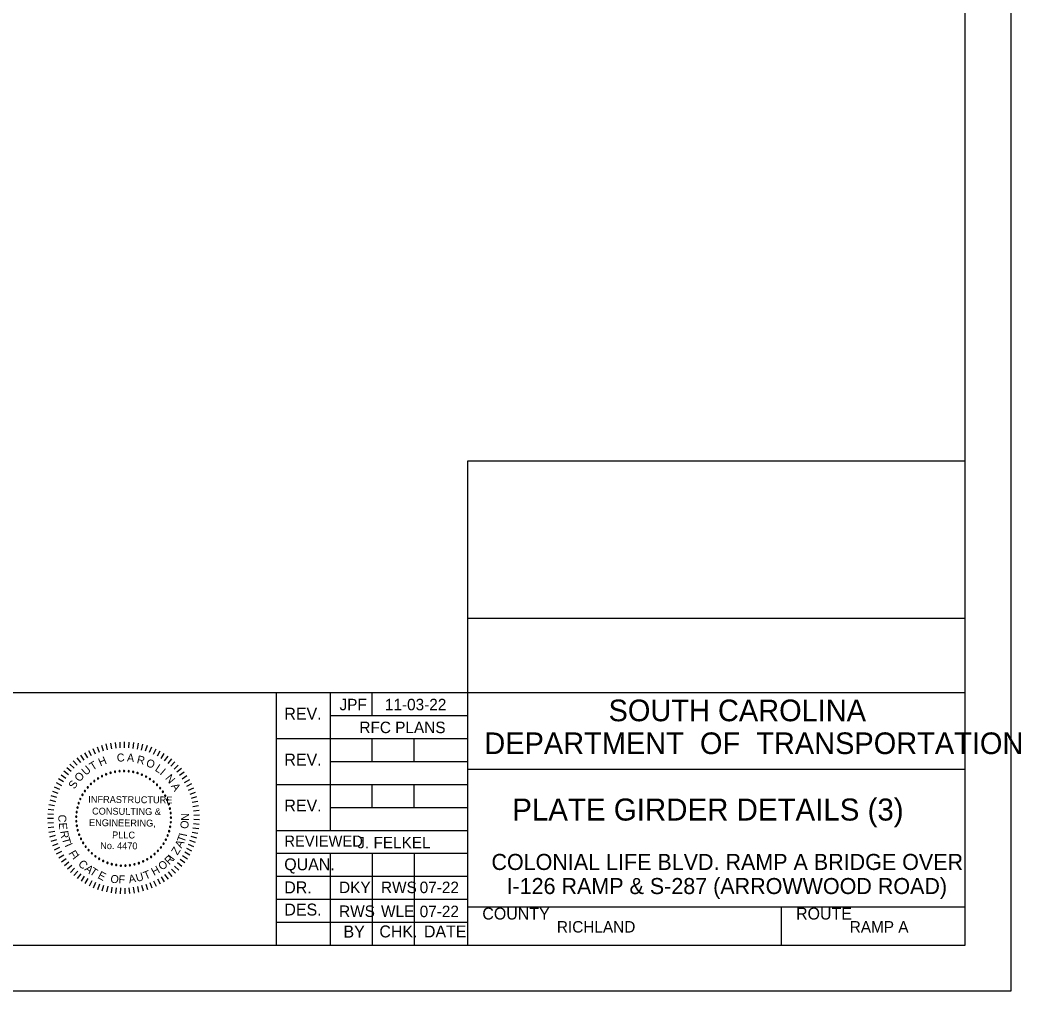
# Model space of a CAD drawing. Extents: x -383 to 7, y -330 to -94.
# Drawn here: x -204.36 to -160.75, y -187.49 to -145.18 of the extents above; entities that cross this region are included whole.
import ezdxf

# ---------------------------------------------------------------- set-up
doc = ezdxf.new("R2010")
doc.units = 0
for name, color, linetype in [('BR_BORDER LINES', 7, 'Continuous'), ('BR_TEXT', 7, 'Continuous'), ('Level 31', 7, 'Continuous')]:
    doc.layers.add(name, color=color, linetype=linetype)

msp = doc.modelspace()

# ---------------------------------------------------------------- linework, layer by layer
at = {"layer": 'BR_BORDER LINES'}
for p, q in [((-163.178, -185.489), (-163.178, -101.489)), ((-184.846, -185.489), (-184.846, -164.383)), ((-184.846, -164.383), (-163.178, -164.383)), ((-184.845, -171.242), (-163.178, -171.242)), ((-214.64, -174.489), (-193.18, -174.489)), ((-193.18, -185.489), (-193.18, -174.489)), ((-193.18, -174.489), (-163.178, -174.489)), ((-190.846, -174.489), (-190.846, -180.489)), ((-189.013, -175.489), (-189.013, -174.489)), ((-190.846, -175.489), (-184.846, -175.489)), ((-193.18, -176.489), (-184.846, -176.489)), ((-189.013, -177.489), (-189.013, -176.489)), ((-187.179, -177.489), (-187.179, -176.489)), ((-190.846, -177.489), (-184.846, -177.489)), ((-184.846, -177.822), (-184.846, -177.822)), ((-184.846, -177.823), (-163.178, -177.823)), ((-193.18, -178.489), (-184.846, -178.489)), ((-189.013, -179.489), (-189.013, -178.489)), ((-187.179, -179.489), (-187.179, -178.489)), ((-190.846, -179.489), (-184.846, -179.489)), ((-193.18, -180.489), (-184.846, -180.489)), ((-193.18, -181.489), (-184.846, -181.489)), ((-190.846, -181.489), (-190.846, -185.489)), ((-189.013, -181.489), (-189.013, -185.489)), ((-187.179, -181.489), (-187.179, -185.489)), ((-193.18, -182.489), (-184.846, -182.489)), ((-193.18, -183.489), (-184.846, -183.489)), ((-184.846, -183.823), (-163.178, -183.823)), ((-184.456, -183.823), (-163.178, -183.823)), ((-171.179, -185.489), (-171.179, -183.823)), ((-193.18, -184.489), (-184.846, -184.489)), ((-297.843, -185.489), (-163.178, -185.489))]:
    msp.add_line(p, q, dxfattribs=at)
at = {"layer": 'BR_TEXT'}
for p, q in [((-201.37, -177.007), (-201.252, -177.233)), ((-201.188, -176.92), (-201.084, -177.153)), ((-201.001, -176.844), (-200.912, -177.082)), ((-200.81, -176.779), (-200.735, -177.023)), ((-200.615, -176.726), (-200.555, -176.974)), ((-200.417, -176.685), (-200.373, -176.936)), ((-200.217, -176.656), (-200.188, -176.909)), ((-200.016, -176.64), (-200.002, -176.894)), ((-199.814, -176.636), (-199.816, -176.89)), ((-199.612, -176.644), (-199.63, -176.898)), ((-199.411, -176.664), (-199.444, -176.917)), ((-199.212, -176.697), (-199.26, -176.947)), ((-199.015, -176.741), (-199.079, -176.988)), ((-198.821, -176.798), (-198.9, -177.04)), ((-198.631, -176.866), (-198.724, -177.103)), ((-198.446, -176.946), (-198.553, -177.177)), ((-198.265, -177.037), (-198.387, -177.261)), ((-202.035, -177.463), (-201.866, -177.654)), ((-201.879, -177.334), (-201.723, -177.535)), ((-201.716, -177.215), (-201.572, -177.425)), ((-201.546, -177.106), (-201.415, -177.324)), ((-198.091, -177.139), (-198.226, -177.355)), ((-197.923, -177.251), (-198.071, -177.458)), ((-197.762, -177.373), (-197.922, -177.571)), ((-202.45, -177.903), (-202.25, -178.06)), ((-202.321, -177.748), (-202.13, -177.917)), ((-202.182, -177.601), (-202.002, -177.781)), ((-197.609, -177.505), (-197.781, -177.693)), ((-197.464, -177.646), (-197.647, -177.823)), ((-197.329, -177.795), (-197.522, -177.961)), ((-202.679, -178.235), (-202.461, -178.366)), ((-202.57, -178.065), (-202.36, -178.21)), ((-197.202, -177.952), (-197.405, -178.106)), ((-197.086, -178.117), (-197.298, -178.258)), ((-196.979, -178.289), (-197.199, -178.417)), ((-202.944, -178.779), (-202.705, -178.869)), ((-202.867, -178.593), (-202.634, -178.696)), ((-202.779, -178.411), (-202.553, -178.529)), ((-196.883, -178.467), (-197.111, -178.581)), ((-196.799, -178.65), (-197.033, -178.75)), ((-203.063, -179.165), (-202.815, -179.225)), ((-203.009, -178.97), (-202.766, -179.045)), ((-196.725, -178.838), (-196.965, -178.924)), ((-196.664, -179.03), (-196.908, -179.101)), ((-203.134, -179.562), (-202.881, -179.592)), ((-203.104, -179.363), (-202.853, -179.407)), ((-196.614, -179.226), (-196.862, -179.282)), ((-196.576, -179.424), (-196.827, -179.465)), ((-196.55, -179.625), (-196.804, -179.65)), ((-203.156, -179.965), (-202.901, -179.964)), ((-203.151, -179.764), (-202.897, -179.777)), ((-196.537, -179.826), (-196.791, -179.836)), ((-196.535, -180.028), (-196.79, -180.022)), ((-203.149, -180.167), (-202.895, -180.15)), ((-203.129, -180.368), (-202.877, -180.335)), ((-203.097, -180.568), (-202.847, -180.52)), ((-196.57, -180.43), (-196.822, -180.393)), ((-196.547, -180.23), (-196.8, -180.208)), ((-203.053, -180.765), (-202.807, -180.701)), ((-202.997, -180.959), (-202.755, -180.881)), ((-196.713, -181.018), (-196.954, -180.936)), ((-196.653, -180.825), (-196.899, -180.758)), ((-196.606, -180.629), (-196.855, -180.577)), ((-202.93, -181.149), (-202.693, -181.056)), ((-202.851, -181.335), (-202.62, -181.228)), ((-202.761, -181.516), (-202.536, -181.395)), ((-196.867, -181.392), (-197.096, -181.281)), ((-196.784, -181.207), (-197.02, -181.111)), ((-202.66, -181.69), (-202.443, -181.556)), ((-202.548, -181.859), (-202.34, -181.711)), ((-197.179, -181.91), (-197.385, -181.759)), ((-197.065, -181.743), (-197.279, -181.605)), ((-196.96, -181.57), (-197.182, -181.446)), ((-202.426, -182.02), (-202.228, -181.86)), ((-202.295, -182.173), (-202.107, -182.002)), ((-202.155, -182.319), (-201.977, -182.136)), ((-202.006, -182.455), (-201.84, -182.262)), ((-197.581, -182.362), (-197.756, -182.176)), ((-197.438, -182.219), (-197.623, -182.045)), ((-197.304, -182.068), (-197.5, -181.905)), ((-201.849, -182.582), (-201.695, -182.379)), ((-201.685, -182.699), (-201.543, -182.487)), ((-201.513, -182.806), (-201.385, -182.586)), ((-201.336, -182.903), (-201.221, -182.675)), ((-198.411, -182.93), (-198.522, -182.701)), ((-198.232, -182.837), (-198.356, -182.615)), ((-198.059, -182.734), (-198.196, -182.519)), ((-197.892, -182.62), (-198.042, -182.414)), ((-197.733, -182.495), (-197.895, -182.3)), ((-201.153, -182.988), (-201.053, -182.754)), ((-200.965, -183.062), (-200.879, -182.822)), ((-200.773, -183.125), (-200.702, -182.88)), ((-200.577, -183.175), (-200.521, -182.927)), ((-200.379, -183.214), (-200.338, -182.962)), ((-200.179, -183.24), (-200.154, -182.987)), ((-199.978, -183.254), (-199.968, -183)), ((-199.776, -183.256), (-199.781, -183.002)), ((-199.574, -183.246), (-199.595, -182.992)), ((-199.373, -183.223), (-199.41, -182.971)), ((-199.174, -183.188), (-199.226, -182.939)), ((-198.978, -183.142), (-199.045, -182.896)), ((-198.785, -183.083), (-198.867, -182.842)), ((-198.596, -183.012), (-198.692, -182.777))]:
    msp.add_line(p, q, dxfattribs=at)
for centre, start, end in [((-200.22, -177.935), 10.6038, 190.6038), ((-200.023, -177.908), 5.0653, 185.0653), ((-200.023, -177.908), 185.0653, 5.0653), ((-199.824, -177.9), 359.5268, 179.5268), ((-199.824, -177.9), 179.5268, 359.5268), ((-199.625, -177.912), 353.9884, 173.9884), ((-199.625, -177.912), 173.9884, 353.9884), ((-199.428, -177.943), 348.4499, 168.4499), ((-201.12, -178.341), 38.2961, 218.2961), ((-201.12, -178.341), 218.2961, 38.2961), ((-200.957, -178.226), 32.7576, 212.7576), ((-200.957, -178.226), 212.7576, 32.7576), ((-200.785, -178.127), 27.2191, 207.2191), ((-200.785, -178.127), 207.2191, 27.2191), ((-200.603, -178.045), 21.6807, 201.6807), ((-200.603, -178.045), 201.6807, 21.6807), ((-200.414, -177.98), 16.1422, 196.1422), ((-200.414, -177.98), 196.1422, 16.1422), ((-200.22, -177.935), 190.6038, 10.6038), ((-199.428, -177.943), 168.4499, 348.4499), ((-199.235, -177.992), 162.9114, 342.9114), ((-199.235, -177.992), 342.9114, 162.9114), ((-199.047, -178.06), 157.373, 337.373), ((-199.047, -178.06), 337.373, 157.373), ((-198.867, -178.146), 151.8345, 331.8345), ((-198.867, -178.146), 331.8345, 151.8345), ((-198.697, -178.249), 146.2961, 326.2961), ((-198.697, -178.249), 326.2961, 146.2961), ((-198.537, -178.368), 140.7576, 320.7576), ((-198.537, -178.368), 320.7576, 140.7576), ((-201.53, -178.774), 54.9114, 234.9114), ((-201.53, -178.774), 234.9114, 54.9114), ((-201.408, -178.617), 49.373, 229.373), ((-201.408, -178.617), 229.373, 49.373), ((-201.27, -178.472), 43.8345, 223.8345), ((-201.27, -178.472), 223.8345, 43.8345), ((-198.389, -178.502), 135.2191, 315.2191), ((-198.389, -178.502), 315.2191, 135.2191), ((-198.255, -178.649), 129.6807, 309.6807), ((-198.255, -178.649), 309.6807, 129.6807), ((-198.135, -178.809), 124.1422, 304.1422), ((-198.135, -178.809), 304.1422, 124.1422), ((-201.727, -179.12), 65.9884, 245.9884), ((-201.727, -179.12), 245.9884, 65.9884), ((-201.637, -178.942), 60.4499, 240.4499), ((-201.637, -178.942), 240.4499, 60.4499), ((-198.032, -178.979), 118.6038, 298.6038), ((-198.032, -178.979), 298.6038, 118.6038), ((-197.945, -179.159), 113.0653, 293.0653), ((-197.945, -179.159), 293.0653, 113.0653), ((-201.854, -179.497), 77.0653, 257.0653), ((-201.854, -179.497), 257.0653, 77.0653), ((-201.8, -179.305), 71.5268, 251.5268), ((-201.8, -179.305), 251.5268, 71.5268), ((-197.876, -179.346), 107.5268, 287.5268), ((-197.876, -179.346), 287.5268, 107.5268), ((-197.826, -179.538), 101.9884, 281.9884), ((-197.826, -179.538), 281.9884, 101.9884), ((-201.906, -179.892), 88.1422, 268.1422), ((-201.904, -180.091), 93.6807, 273.6807), ((-201.89, -179.693), 82.6038, 262.6038), ((-201.906, -179.892), 268.1422, 88.1422), ((-201.904, -180.091), 273.6807, 93.6807), ((-201.89, -179.693), 262.6038, 82.6038), ((-197.795, -179.735), 96.4499, 276.4499), ((-197.782, -179.934), 90.9114, 270.9114), ((-197.795, -179.735), 276.4499, 96.4499), ((-197.782, -179.934), 270.9114, 90.9114), ((-201.882, -180.289), 99.2191, 279.2191), ((-201.882, -180.289), 279.2191, 99.2191), ((-201.841, -180.484), 104.7576, 284.7576), ((-201.841, -180.484), 284.7576, 104.7576), ((-197.86, -180.525), 74.2961, 254.2961), ((-197.86, -180.525), 254.2961, 74.2961), ((-197.815, -180.331), 79.8345, 259.8345), ((-197.815, -180.331), 259.8345, 79.8345), ((-197.789, -180.133), 85.373, 265.373), ((-197.789, -180.133), 265.373, 85.373), ((-201.781, -180.675), 110.2961, 290.2961), ((-201.781, -180.675), 290.2961, 110.2961), ((-201.703, -180.858), 115.8345, 295.8345), ((-201.703, -180.858), 295.8345, 115.8345), ((-198.005, -180.896), 63.2191, 243.2191), ((-198.005, -180.896), 243.2191, 63.2191), ((-197.924, -180.714), 68.7576, 248.7576), ((-197.924, -180.714), 248.7576, 68.7576), ((-201.608, -181.033), 121.373, 301.373), ((-201.608, -181.033), 301.373, 121.373), ((-201.497, -181.199), 126.9114, 306.9114), ((-201.497, -181.199), 306.9114, 126.9114), ((-201.37, -181.352), 132.4499, 312.4499), ((-201.37, -181.352), 312.4499, 132.4499), ((-198.349, -181.383), 46.6038, 226.6038), ((-198.349, -181.383), 226.6038, 46.6038), ((-198.219, -181.232), 52.1422, 232.1422), ((-198.219, -181.232), 232.1422, 52.1422), ((-198.104, -181.069), 57.6807, 237.6807), ((-198.104, -181.069), 237.6807, 57.6807), ((-201.228, -181.493), 137.9884, 317.9884), ((-201.228, -181.493), 317.9884, 137.9884), ((-201.074, -181.619), 143.5268, 323.5268), ((-201.074, -181.619), 323.5268, 143.5268), ((-200.909, -181.73), 149.0653, 329.0653), ((-200.909, -181.73), 329.0653, 149.0653), ((-200.733, -181.825), 154.6038, 334.6038), ((-200.733, -181.825), 334.6038, 154.6038), ((-198.995, -181.842), 24.4499, 204.4499), ((-198.995, -181.842), 204.4499, 24.4499), ((-198.817, -181.752), 29.9884, 209.9884), ((-198.817, -181.752), 209.9884, 29.9884), ((-198.649, -181.644), 35.5268, 215.5268), ((-198.649, -181.644), 215.5268, 35.5268), ((-198.493, -181.521), 41.0653, 221.0653), ((-198.493, -181.521), 221.0653, 41.0653), ((-200.549, -181.902), 160.1422, 340.1422), ((-200.549, -181.902), 340.1422, 160.1422), ((-200.359, -181.961), 165.6807, 345.6807), ((-200.359, -181.961), 345.6807, 165.6807), ((-200.164, -182.001), 171.2191, 351.2191), ((-200.164, -182.001), 351.2191, 171.2191), ((-199.965, -182.022), 176.7576, 356.7576), ((-199.965, -182.022), 356.7576, 176.7576), ((-199.766, -182.024), 2.2961, 182.2961), ((-199.766, -182.024), 182.2961, 2.2961), ((-199.568, -182.007), 7.8345, 187.8345), ((-199.568, -182.007), 187.8345, 7.8345), ((-199.372, -181.971), 13.373, 193.373), ((-199.372, -181.971), 193.373, 13.373), ((-199.18, -181.916), 18.9114, 198.9114), ((-199.18, -181.916), 198.9114, 18.9114)]:
    msp.add_arc(centre, 0.028, start, end, dxfattribs=at)
at = {"layer": 'Level 31'}
msp.add_line((-174.011, -179.583), (-174.011, -179.583), dxfattribs=at)
msp.add_lwpolyline([(-305.176, -187.489), (-161.176, -187.489), (-161.176, -99.489), (-305.176, -99.489)], close=True, dxfattribs=at)

# ---------------------------------------------------------------- texts
at = {"layer": 'BR_TEXT'}
for s, height, p in [('JPF', 0.5, (-190.438, -175.257)), ('11-03-22', 0.5, (-188.461, -175.257)), ('SOUTH CAROLINA', 0.94348, (-178.718, -175.735)), ('REV.', 0.52, (-192.841, -175.667)), ('RFC PLANS', 0.5, (-189.572, -176.253)), ('DEPARTMENT  OF  TRANSPORTATION', 0.94348, (-184.129, -177.166)), ('REV.', 0.52, (-192.841, -177.667)), ('REV.', 0.52, (-192.841, -179.667)), ('PLATE GIRDER DETAILS (3)', 0.96, (-182.913, -180.063)), ('REVIEWED', 0.48, (-192.843, -181.195)), ('J. FELKEL', 0.5, (-189.664, -181.272)), ('QUAN.', 0.52, (-192.846, -182.229)), ('COLONIAL LIFE BLVD. RAMP A BRIDGE OVER', 0.7, (-183.82, -182.216)), ('I-126 RAMP & S-287 (ARROWWOOD ROAD)', 0.7, (-183.162, -183.266)), ('DR.', 0.52, (-192.845, -183.235)), ('DKY', 0.5, (-190.457, -183.224)), ('RWS', 0.5, (-188.632, -183.224)), ('07-22', 0.5, (-186.946, -183.224)), ('DES.', 0.52, (-192.841, -184.2)), ('RWS', 0.5, (-190.457, -184.263)), ('WLE', 0.5, (-188.63, -184.263)), ('07-22', 0.5, (-186.946, -184.272)), ('COUNTY', 0.52, (-184.217, -184.376)), ('ROUTE', 0.52, (-170.55, -184.376)), ('RICHLAND', 0.5, (-180.968, -184.944)), ('RAMP A', 0.5, (-168.212, -184.944)), ('BY', 0.52, (-190.265, -185.161)), ('CHK.', 0.52, (-188.701, -185.156)), ('DATE', 0.52, (-186.761, -185.156))]:
    msp.add_text(s, height=height, dxfattribs=at).set_placement(p)
for s, height, rotation, p in [('T', 0.349, 31.8182, (-201.196, -177.894)), ('H', 0.349, 22.7882, (-200.857, -177.704)), ('C', 0.349, 4.7281, (-200.126, -177.506)), ('A', 0.349, 355.6981, (-199.708, -177.486)), ('R', 0.349, 346.6681, (-199.291, -177.554)), ('O', 0.349, 337.638, (-198.9, -177.673)), ('U', 0.349, 40.8482, (-201.49, -178.119)), ('L', 0.349, 327.108, (-198.504, -177.875)), ('I', 0.349, 319.578, (-198.294, -178.026)), ('S', 0.349, 58.9083, (-201.979, -178.715)), ('O', 0.349, 49.8782, (-201.757, -178.403)), ('N', 0.349, 310.548, (-198.051, -178.23)), ('A', 0.349, 301.5179, (-197.791, -178.559)), ('INFRASTRUCTURE', 0.29909, 359.5268, (-201.385, -179.286)), ('CONSULTING &', 0.29909, 359.5268, (-201.22, -179.8)), ('C', 0.349, 267.025, (-202.679, -179.795)), ('ENGINEERING,', 0.29909, 359.5268, (-201.354, -180.302)), ('O', 0.349, 83.2085, (-197.038, -180.44)), ('N', 0.349, 89.2085, (-196.993, -180.074)), ('E', 0.349, 273.025, (-202.662, -180.161)), ('R', 0.349, 279.025, (-202.61, -180.531)), ('T', 0.349, 285.025, (-202.541, -180.846)), ('PLLC', 0.2991, 359.5268, (-200.347, -180.836)), ('T', 0.349, 69.3954, (-197.203, -181.047)), ('I', 0.349, 77.9093, (-197.1, -180.777)), ('I', 0.349, 293.7713, (-202.422, -181.138)), ('F', 0.349, 299.7713, (-202.257, -181.482)), ('No. 4470', 0.2991, 359.5268, (-200.865, -181.304)), ('Z', 0.349, 57.3954, (-197.501, -181.594)), ('A', 0.349, 63.3954, (-197.326, -181.288)), ('I', 0.349, 308.5268, (-202.089, -181.698)), ('C', 0.349, 314.5268, (-201.851, -181.978)), ('O', 0.349, 38.5268, (-198.169, -182.254)), ('R', 0.349, 44.5268, (-197.863, -182.014)), ('I', 0.349, 52.3339, (-197.665, -181.825)), ('A', 0.349, 320.5268, (-201.575, -182.213)), ('T', 0.349, 326.5268, (-201.357, -182.366)), ('E', 0.349, 332.5268, (-201.003, -182.558)), ('T', 0.349, 22.5268, (-198.894, -182.645)), ('H', 0.349, 28.5268, (-198.522, -182.478)), ('O', 0.349, 350.5268, (-200.442, -182.753)), ('F', 0.349, 356.5268, (-200.076, -182.79)), ('A', 0.349, 10.5268, (-199.597, -182.796)), ('U', 0.349, 16.5268, (-199.261, -182.742))]:
    msp.add_text(s, height=height, rotation=rotation, dxfattribs=at).set_placement(p)

doc.saveas('drawing.dxf')
